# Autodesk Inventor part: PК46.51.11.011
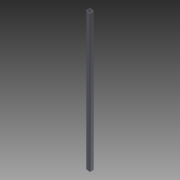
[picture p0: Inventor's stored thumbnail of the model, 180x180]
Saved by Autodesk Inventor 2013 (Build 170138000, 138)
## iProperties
Shininess: 64.0
Length Units: 11269
Angle Units: 11279
Time Units: 11290
Mass Units: 11283
Length Display Precision: 3
Angle Display Precision: 2
Compacted: True
Part Number: PК46.51.11.011
Document SubType Name: Modeling
Created: 2004-07
Material: Steel, Mild
Designer: =<Author>
Manufacturer: Standard
Standards Organization: Custom
Description: pipe
Density: 7.86 g/cm^3
Mass: 1704.38 g
Surface Area: 2172.77 cm^2
Volume: 216.843 cm^3
Density: 0.0
Volumn: 0.0
Area: 0.0
PropertySet Name: Model Information
Control State: 0
Master: False
Checked Out: False
Checked Out Date: 2008-10-15
Last Check In Date: 2008-10-15
Author: PVitaliy
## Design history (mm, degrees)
sketch "Эскиз1"
  geometry: L1 (4, 0)-(26, 0); L2 (30, 4)-(30, 26); L3 (26, 30)-(4, 30); L4 (0, 26)-(0, 4); L5 (2, 26)-(2, 4); L6 (4, 2)-(26, 2); L7 (28, 4)-(28, 26); L8 (26, 28)-(4, 28); A1 r 4 centre (4, 26) between (4, 30) and (0, 26); A2 r 4 centre (26, 26) between (30, 26) and (26, 30); A3 r 4 centre (26, 4) between (26, 0) and (30, 4); A4 r 4 centre (4, 4) between (0, 4) and (4, 0); A5 r 2 centre (4, 26) between (4, 28) and (2, 26); A6 r 2 centre (4, 4) between (2, 4) and (4, 2); A7 r 2 centre (26, 4) between (26, 2) and (28, 4); A8 r 2 centre (26, 26) between (28, 26) and (26, 28); 3 further points
  constraints: 16 end point, 16 point on circle, 8 centre point, 8 tangent, 6 point on line, 4 parallel, 2 equal radius, 2 perpendicular, 1 horizontal, 8 other
  dimensions: "d0" = 30 distance of point (0, 30) point (0, 0); "d1" = 30 distance of point (0, 0) point (30, 0); "d2" = 4 radius of A1; "d3" = 4 radius of A2; "d4" = 2 distance between parallel lines of L1 L6
extrude "Выдавливание1" new body sketch "Эскиз1" distance "d5" = 1020; taper "d6" = 0 deg
sketch "Эскиз2"
  geometry: L1 (-22, 0)-(0, 0) reference; L2 (4, 1020)-(4, 0) reference; L3 (-26, 1020)-(-26, 0) reference; L4 (-22, 0)-(-26, 0) reference; L5 (4, 0)-(0, 0) reference; L6 (-26, 0)-(4, 5.29); L7 (0, 1020)-(-22, 1020) reference; L8 (0, 1020)-(4, 1020) reference; L9 (-26, 1020)-(-22, 1020) reference; L10 (4, 1020)-(-26, 1014.71)
  constraints: 4 end point, 2 point on line
  dimensions: "d7" = 10 deg angle of L6 L1; "d10" = 10 deg angle of L7 L10
extrude "Выдавливание2" cut sketch "Эскиз2" stored distance "d8" = 10; taper "d9" = 0 deg
body "Solid1"
